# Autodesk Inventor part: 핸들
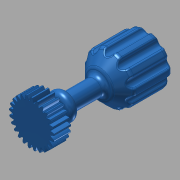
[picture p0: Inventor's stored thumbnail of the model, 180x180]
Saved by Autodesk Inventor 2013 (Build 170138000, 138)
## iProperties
Created: 2017-04
Part Number: 핸들
Material: 강철, 연강
Document SubType Name: Modeling
Designer: mduedu
Categories: <?xml version="1.0" encoding="UTF-16"?> <MemberInstance><Categories><FamilyTemplate><FamilyTemplateParameter ValueType="xs:double" Id="1" ObjectReferenceKey="da
Density: 1 g/cm^3
CustomPartVersion: 1
Author: mduedu
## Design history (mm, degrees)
sketch "Sketch1"
  geometry: C1 r 13.5 at (0, 0)
  constraints: 1 centre point
  dimensions: "d0" = 27 diameter of C1 (= da_da)
extrude "Extrusion1" new body sketch "Sketch1" distance "d1" = 10 (= da_b); taper "d2" = 0 deg
workplane "Work Plane2"
sketch "Sketch2"
  geometry: C1 r 13.5 at (0, 0) reference; C2 r 12.5 at (0, 0)
  constraints: 1 centre point, 1 coincident
  dimensions: "d3" = 25 diameter of C2 (= da_dw)
feature "피치 지름" sketch "Sketch2" dims "d4" = 10, "d5" = 0
workplane "Work Plane8"
workplane "Work Plane9"
feature "스퍼 기어" dims "da_b" = 10, "da_d" = 25, "da_aw" = 25, "da_da" = 27, "da_df" = 22.5, "da_dw" = 25, angle "da_beta" = 0 deg, "da_lefttooth" = 0, "da_righttooth" = 0
sketch "스케치3"
  geometry: C1 r 5 at (0, 0); 1 further point
  constraints: 1 centre point, 1 coincident
  dimensions: "d49" = 10 diameter of C1
extrude "돌출2" join sketch "스케치3" distance "d50" = 60; taper "d51" = 0 deg
sketch "스케치4"
  geometry: C1 r 15 at (0, 0); 1 further point
  constraints: 1 centre point, 1 coincident
  dimensions: "d52" = 30 diameter of C1
extrude "돌출3" join sketch "스케치4" distance "d53" = 30; taper "d54" = 0 deg
chamfer "모따기1" distance "d55" = 7; stored, may be unused: second distance "d56" = 2, angle "d57" = 45 deg
sketch "스케치5"
  geometry: L1 (0, 2.2)-(0, -13.2) reference; L2 (0, -5)-(8, -5); L3 (8, -5)-(8, -11); L4 (8, -11)-(0, -11); L5 (0, -11)-(0, -5); 1 further point
  constraints: 8 end point, 2 parallel, 1 horizontal, 1 perpendicular, 1 point on line
  dimensions: "d58" = 5 distance from line of L2 point (0, 0); "d59" = 6 distance of L2.end L3.end; "d60" = 16 diameter of L3 L1
revolve "회전1" sketch "스케치5" stored, may be unused: angle "d61" = 90 deg
fillet "모깎기1" dims "d62" = 3
fillet "모깎기2" dims "d65" = 3
fillet "모깎기3" dims "d72" = 3
sketch "스케치6"
  geometry: C1 r 2.5 at (0, 15); 2 further points
  constraints: 2 vertical alignment, 1 centre point, 1 other
  dimensions: "d66" = 5 diameter of C1
extrude "돌출4" cut sketch "스케치6" stored distance "d67" = 35; taper "d68" = 0 deg
fillet "모깎기4" dims "d73" = 1
body "Solid1"
pattern_circular "원형 패턴2" dims angle "d75" = 360 deg
body "Srf1"
other parameters: "d16" = 25 (= da_aw), "d17" = 0, "d34" = 1.25664 (computed from da_z), "d39" = 0, "d41" = 0, "d43" = 25 (= da_aw), "d46" = 25 (= da_aw), "d47" = 0, "d48" = 0
